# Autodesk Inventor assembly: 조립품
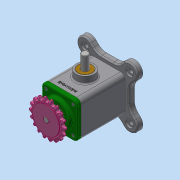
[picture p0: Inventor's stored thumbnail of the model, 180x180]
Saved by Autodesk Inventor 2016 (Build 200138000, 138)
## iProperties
Created: 2019-11
Part Number: 조립품
Material: 일반
Document SubType Name: Assembly
Designer: user
Author: user
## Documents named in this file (11)
- C:\Users\user\Desktop\491109V1002\조립품.iam
- C:\Users\user\Desktop\491109V1002\베어링 6203.ipt
- C:\Users\user\Desktop\491109V1002\본체.ipt
- C:\Users\user\Desktop\491109V1002\볼트 M4.ipt
- C:\Users\user\Desktop\491109V1002\부시.ipt
- C:\Users\user\Desktop\491109V1002\스프로킷.ipt
- C:\Users\user\Desktop\491109V1002\슬라이더.ipt
- C:\Users\user\Desktop\491109V1002\오일 실.ipt
- C:\Users\user\Desktop\491109V1002\커버.ipt
- C:\Users\user\Desktop\491109V1002\키 4 x 4 x 14.ipt
- C:\Users\user\Desktop\491109V1002\편심축.ipt
